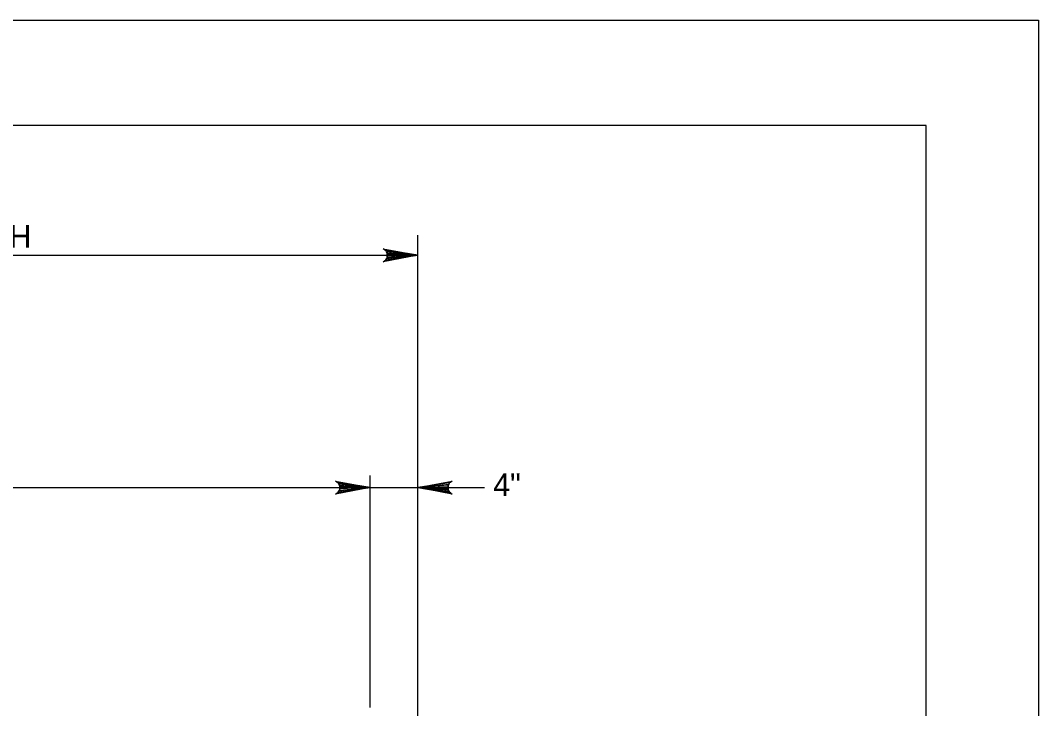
# Model space of a CAD drawing. Extents: x 638167 to 640248, y 296544 to 298920.
# Drawn here: x 639703.7 to 639848.8, y 298822.4 to 298920.5 of the extents above; entities that cross this region are included whole.
import ezdxf

# ---------------------------------------------------------------- set-up
doc = ezdxf.new("R2010")
doc.units = 0
doc.layers.add('1', color=7, linetype='Continuous')
doc.layers.add('PLT-BNDY', color=7, linetype='Continuous')

msp = doc.modelspace()

# ---------------------------------------------------------------- linework, layer by layer
at = {"layer": '1'}
for p, q in [((639832.78, 298905.48), (639046.78, 298905.48)), ((639832.78, 298341.48), (639832.78, 298905.48)), ((639760.33, 298781.09), (639760.33, 298889.87)), ((639563.48, 298887), (639760.33, 298887)), ((639753.55, 298822.52), (639753.55, 298855.62)), ((639563.48, 298853.88), (639769.86, 298853.88))]:
    msp.add_line(p, q, dxfattribs=at)
for points in [[(639760.33, 298887), (639755.39, 298886.08), (639755.58, 298886.21), (639755.77, 298886.34), (639755.87, 298886.51), (639755.97, 298886.67), (639756, 298886.84), (639756.03, 298887), (639756, 298887.17), (639755.97, 298887.33), (639755.87, 298887.5), (639755.77, 298887.66), (639755.58, 298887.79), (639755.39, 298887.93), (639760.33, 298887), (639755.58, 298887.79), (639755.77, 298887.66), (639760.33, 298887), (639755.87, 298887.5), (639755.97, 298887.33), (639760.33, 298887), (639756, 298887.17), (639756.03, 298887), (639760.33, 298887), (639756, 298886.84), (639755.97, 298886.67), (639760.33, 298887), (639755.87, 298886.51), (639755.77, 298886.34), (639760.33, 298887), (639755.58, 298886.21)], [(639753.55, 298853.88), (639748.62, 298852.95), (639748.81, 298853.08), (639749, 298853.21), (639749.1, 298853.38), (639749.2, 298853.54), (639749.23, 298853.71), (639749.25, 298853.88), (639749.23, 298854.04), (639749.2, 298854.21), (639749.1, 298854.37), (639749, 298854.54), (639748.81, 298854.67), (639748.62, 298854.8), (639753.55, 298853.88), (639748.81, 298854.67), (639749, 298854.54), (639753.55, 298853.88), (639749.1, 298854.37), (639749.2, 298854.21), (639753.55, 298853.88), (639749.23, 298854.04), (639749.25, 298853.88), (639753.55, 298853.88), (639749.23, 298853.71), (639749.2, 298853.54), (639753.55, 298853.88), (639749.1, 298853.38), (639749, 298853.21), (639753.55, 298853.88), (639748.81, 298853.08)], [(639760.33, 298853.88), (639765.26, 298854.8), (639765.07, 298854.67), (639764.88, 298854.54), (639764.78, 298854.37), (639764.68, 298854.21), (639764.65, 298854.04), (639764.63, 298853.88), (639764.65, 298853.71), (639764.68, 298853.54), (639764.78, 298853.38), (639764.88, 298853.21), (639765.07, 298853.08), (639765.26, 298852.95), (639760.33, 298853.88), (639765.07, 298853.08), (639764.88, 298853.21), (639760.33, 298853.88), (639764.78, 298853.38), (639764.68, 298853.54), (639760.33, 298853.88), (639764.65, 298853.71), (639764.63, 298853.88), (639760.33, 298853.88), (639764.65, 298854.04), (639764.68, 298854.21), (639760.33, 298853.88), (639764.78, 298854.37), (639764.88, 298854.54), (639760.33, 298853.88), (639765.07, 298854.67)]]:
    msp.add_lwpolyline(points, dxfattribs=at)
at = {"layer": 'PLT-BNDY'}
msp.add_lwpolyline([(639007.78, 298920.48), (639848.78, 298920.48), (639848.78, 298326.48), (639007.78, 298326.48)], close=True, dxfattribs=at)

# ---------------------------------------------------------------- texts
at = {"layer": '1'}
for s, height, p in [('BARRIER MOMENT SLAB WIDTH', 3.2256, (639638.19, 298888.08)), ('4"', 3.226, (639771.09, 298852.67))]:
    msp.add_text(s, height=height, dxfattribs=at).set_placement(p)

doc.saveas('drawing.dxf')
